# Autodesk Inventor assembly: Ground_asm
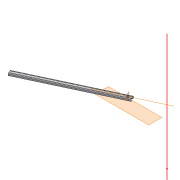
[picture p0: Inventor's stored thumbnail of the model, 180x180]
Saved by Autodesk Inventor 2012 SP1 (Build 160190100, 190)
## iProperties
Created: 2006-09
Part Number: Ground_asm
Document SubType Name: Assembly
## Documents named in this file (3)
- D:\Backup\CMU Work Temp\XX\Inv2012DynSim\Sub-Assemblies\Ground_asm.iam
- D:\Backup\CMU Work Temp\XX\Inv2012DynSim\Parts\Ground.ipt
- D:\Backup\CMU Work Temp\XX\Inv2012DynSim\Parts\Guide.ipt
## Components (2 placed, 2 different names)
1. Ground:1 — Mate:3
2. Guide:1 — Mate:3
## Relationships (1: Mate 1)
- Mate:3: Ground:1 ↔ Guide:1
